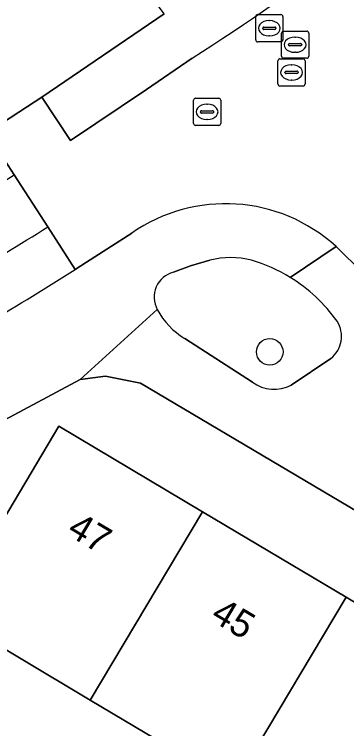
# Model space of a CAD drawing. Extents: x 161354 to 162026, y 386504 to 387460.
# Drawn here: x 161573.11 to 161585.34, y 386823.37 to 386849.65 of the extents above; entities that cross this region are included whole.
import ezdxf

# ---------------------------------------------------------------- set-up
doc = ezdxf.new("R2010")
doc.units = 0
for name, color, linetype in [('IMGEO_Boom', 7, 'Continuous'), ('IMGEO_Erf', 7, 'Continuous'), ('IMGEO_Groenvoorziening', 7, 'Continuous'), ('IMGEO_Pand', 7, 'Continuous'), ('IMGEO_Pand_nummerreeks', 7, 'Continuous'), ('IMGEO_Rijbaan_lokaal_gesloten', 7, 'Continuous'), ('IMGEO_Rijbaan_lokaal_open', 7, 'Continuous'), ('IMGEO_Rioolput', 7, 'Continuous'), ('IMGEO_Voetpad_open', 7, 'Continuous')]:
    doc.layers.add(name, color=color, linetype=linetype)

msp = doc.modelspace()

# ---------------------------------------------------------------- linework, layer by layer
at = {"layer": 'IMGEO_Boom'}
msp.add_circle((161582.505, 386837.229), 0.489, dxfattribs=at)
at = {"layer": 'IMGEO_Erf'}
for points in [[(161582.873, 386802.656), (161585.359, 386801.185), (161593.139, 386814.497), (161598.54, 386823.761), (161577.757, 386836.079), (161576.468, 386836.339), (161575.538, 386836.218), (161567.714, 386832.035), (161560.908, 386828.506), (161561.042, 386828.079), (161562.963, 386821.942), (161566.488, 386823.051), (161567.989, 386818.282), (161568.843, 386815.568), (161567.681, 386815.202), (161568.624, 386812.203), (161569.072, 386810.78), (161573.417, 386808.223), (161578.663, 386805.134)], [(161586.473, 386818.127), (161581.19, 386821.273), (161575.907, 386824.418), (161570.624, 386827.563), (161574.749, 386834.493), (161580.032, 386831.347), (161585.315, 386828.202), (161590.598, 386825.057), (161595.881, 386821.911), (161591.756, 386814.982)]]:
    msp.add_lwpolyline(points, close=True, dxfattribs=at)
at = {"layer": 'IMGEO_Groenvoorziening'}
for points in [[(161580.307, 386840.6), (161579.593, 386840.392), (161578.962, 386840.157)], [(161579.382, 386837.723), (161581.867, 386836.119)], [(161583.296, 386836.004), (161584.749, 386836.986)]]:
    msp.add_lwpolyline(points, dxfattribs=at)
for centre, radius, start, end in [((161581.073, 386837.677), 3.022, 75.3835, 104.6914), ((161580.176, 386834.963), 5.877, 58.3439, 73.5893), ((161579.203, 386839.24), 0.948, 104.7308, 208.3977), ((161580.163, 386834.932), 5.911, 35.4172, 58.4023), ((161580.785, 386840.071), 2.735, 207.9451, 239.1342), ((161584.12, 386837.797), 1.027, 307.8119, 33.0602), ((161582.672, 386837.183), 1.334, 232.8898, 297.9081)]:
    msp.add_arc(centre, radius, start, end, dxfattribs=at)
at = {"layer": 'IMGEO_Pand'}
for points in [[(161580.032, 386831.347), (161574.749, 386834.493), (161570.624, 386827.563), (161575.907, 386824.418)], [(161585.315, 386828.202), (161580.032, 386831.347), (161575.907, 386824.418), (161581.19, 386821.273)], [(161581.19, 386821.273), (161586.473, 386818.127), (161590.598, 386825.057), (161585.315, 386828.202)]]:
    msp.add_lwpolyline(points, close=True, dxfattribs=at)
at = {"layer": 'IMGEO_Rijbaan_lokaal_gesloten'}
for points in [[(161578.619, 386849.66), (161574.129, 386846.599), (161575.172, 386845.007), (161577.974, 386846.882), (161579.649, 386848.034)], [(161573.11, 386843.737), (161572.098, 386845.287), (161570.397, 386844.237)], [(161575.348, 386840.265), (161574.346, 386841.828)]]:
    msp.add_lwpolyline(points, dxfattribs=at)
for centre, radius, start, end in [((161538.721, 386912.606), 76.45, 302.3682, 313.17373), ((161483.765, 386989.11), 170.634, 294.48882, 301.57465), ((161507.605, 386948.155), 125.538, 298.78933, 302.11626), ((161526.3, 386916.738), 90.851, 298.00279, 302.67491)]:
    msp.add_arc(centre, radius, start, end, dxfattribs=at)
at = {"layer": 'IMGEO_Rijbaan_lokaal_open'}
for points in [[(161579.649, 386848.034), (161577.974, 386846.882), (161575.172, 386845.007), (161574.129, 386846.599), (161572.098, 386845.287), (161573.11, 386843.737), (161574.346, 386841.828), (161575.348, 386840.265), (161575.762, 386840.525), (161577.428, 386841.593)], [(161584.945, 386841.103), (161587.875, 386838.211), (161592.118, 386842.451), (161590.731, 386843.944)], [(161574.346, 386841.828), (161573.11, 386843.737)]]:
    msp.add_lwpolyline(points, dxfattribs=at)
for centre, radius, start, end in [((161538.721, 386912.606), 76.45, 302.3682, 313.17373), ((161483.765, 386989.11), 170.634, 294.48882, 301.57465), ((161580.88, 386836.646), 6.033, 47.6359, 124.905), ((161507.605, 386948.155), 125.538, 298.78933, 302.11626)]:
    msp.add_arc(centre, radius, start, end, dxfattribs=at)
at = {"layer": 'IMGEO_Rioolput'}
for p, q in [((161581.989, 386848.708), (161581.989, 386849.56)), ((161582.064, 386849.634), (161582.916, 386849.634)), ((161582.477, 386849.414), (161582.502, 386849.414)), ((161582.99, 386849.56), (161582.99, 386848.708)), ((161582.248, 386849.128), (161582.248, 386849.14)), ((161582.291, 386849.177), (161582.689, 386849.177)), ((161582.732, 386849.14), (161582.732, 386849.128)), ((161582.686, 386849.091), (161582.288, 386849.091)), ((161582.939, 386848.103), (161582.939, 386848.955)), ((161583.014, 386849.029), (161583.866, 386849.029)), ((161583.94, 386848.955), (161583.94, 386848.103)), ((161582.916, 386848.634), (161582.064, 386848.634)), ((161582.5, 386848.854), (161582.475, 386848.854)), ((161583.427, 386848.809), (161583.452, 386848.809)), ((161583.198, 386848.523), (161583.198, 386848.535)), ((161583.636, 386848.486), (161583.238, 386848.486)), ((161583.241, 386848.572), (161583.639, 386848.572)), ((161583.682, 386848.535), (161583.682, 386848.523)), ((161583.45, 386848.249), (161583.425, 386848.249)), ((161582.807, 386847.083), (161582.807, 386847.935)), ((161582.882, 386848.009), (161583.734, 386848.009)), ((161583.866, 386848.029), (161583.014, 386848.029)), ((161583.808, 386847.935), (161583.808, 386847.083)), ((161583.295, 386847.789), (161583.32, 386847.789)), ((161583.066, 386847.503), (161583.066, 386847.515)), ((161583.504, 386847.466), (161583.106, 386847.466)), ((161583.109, 386847.552), (161583.507, 386847.552)), ((161583.55, 386847.515), (161583.55, 386847.503)), ((161583.318, 386847.229), (161583.293, 386847.229)), ((161583.734, 386847.009), (161582.882, 386847.009)), ((161579.776, 386846.557), (161580.628, 386846.557)), ((161579.701, 386845.631), (161579.701, 386846.483)), ((161580.189, 386846.337), (161580.214, 386846.337)), ((161580.702, 386846.483), (161580.702, 386845.631)), ((161579.96, 386846.051), (161579.96, 386846.063)), ((161580.398, 386846.014), (161580, 386846.014)), ((161580.003, 386846.1), (161580.401, 386846.1)), ((161580.444, 386846.063), (161580.444, 386846.051)), ((161580.212, 386845.777), (161580.187, 386845.777)), ((161580.628, 386845.557), (161579.776, 386845.557))]:
    msp.add_line(p, q, dxfattribs=at)
for points in [[(161581.989, 386848.708), (161581.989, 386849.56)], [(161582.064, 386849.634), (161582.916, 386849.634)], [(161582.99, 386849.56), (161582.99, 386848.708)], [(161582.939, 386848.103), (161582.939, 386848.955)], [(161583.014, 386849.029), (161583.866, 386849.029)], [(161583.94, 386848.955), (161583.94, 386848.103)], [(161582.916, 386848.634), (161582.064, 386848.634)], [(161582.807, 386847.083), (161582.807, 386847.935)], [(161582.882, 386848.009), (161583.734, 386848.009)], [(161583.866, 386848.029), (161583.014, 386848.029)], [(161583.808, 386847.935), (161583.808, 386847.083)], [(161583.734, 386847.009), (161582.882, 386847.009)], [(161579.776, 386846.557), (161580.628, 386846.557)], [(161579.701, 386845.631), (161579.701, 386846.483)], [(161580.702, 386846.483), (161580.702, 386845.631)], [(161580.628, 386845.557), (161579.776, 386845.557)]]:
    msp.add_lwpolyline(points, dxfattribs=at)
for centre, radius, start, end in [((161582.066, 386849.558), 0.0765, 91.552, 178.448), ((161582.066, 386849.558), 0.0765, 91.552, 178.448), ((161582.914, 386849.558), 0.0765, 1.552, 88.448), ((161582.914, 386849.558), 0.0765, 1.552, 88.448), ((161582.288, 386849.137), 0.0403, 85.8775, 175.7526), ((161582.693, 386849.139), 0.0386, 1.7309, 96.639), ((161582.285, 386849.127), 0.0366, 178.938, 274.7102), ((161582.689, 386849.134), 0.043, 264.8664, 352.4533), ((161583.016, 386848.953), 0.0765, 91.552, 178.448), ((161583.016, 386848.953), 0.0765, 91.552, 178.448), ((161583.864, 386848.953), 0.0765, 1.552, 88.448), ((161583.864, 386848.953), 0.0765, 1.552, 88.448), ((161582.066, 386848.71), 0.0765, 181.552, 268.448), ((161582.066, 386848.71), 0.0765, 181.552, 268.448), ((161582.914, 386848.71), 0.0765, 271.552, 358.448), ((161582.914, 386848.71), 0.0765, 271.552, 358.448), ((161583.238, 386848.532), 0.0403, 85.8775, 175.7526), ((161583.235, 386848.522), 0.0366, 178.938, 274.7102), ((161583.639, 386848.529), 0.043, 264.8664, 352.4533), ((161583.643, 386848.534), 0.0386, 1.7309, 96.639), ((161583.016, 386848.105), 0.0765, 181.552, 268.448), ((161583.016, 386848.105), 0.0765, 181.552, 268.448), ((161583.864, 386848.105), 0.0765, 271.552, 358.448), ((161583.864, 386848.105), 0.0765, 271.552, 358.448), ((161582.884, 386847.933), 0.0765, 91.552, 178.448), ((161582.884, 386847.933), 0.0765, 91.552, 178.448), ((161583.732, 386847.933), 0.0765, 1.552, 88.448), ((161583.732, 386847.933), 0.0765, 1.552, 88.448), ((161583.106, 386847.512), 0.0403, 85.8775, 175.7526), ((161583.103, 386847.502), 0.0366, 178.938, 274.7102), ((161583.507, 386847.509), 0.043, 264.8664, 352.4533), ((161583.511, 386847.514), 0.0386, 1.7309, 96.639), ((161582.884, 386847.085), 0.0765, 181.552, 268.448), ((161582.884, 386847.085), 0.0765, 181.552, 268.448), ((161583.732, 386847.085), 0.0765, 271.552, 358.448), ((161583.732, 386847.085), 0.0765, 271.552, 358.448), ((161579.778, 386846.481), 0.0765, 91.552, 178.448), ((161579.778, 386846.481), 0.0765, 91.552, 178.448), ((161580.626, 386846.481), 0.0765, 1.552, 88.448), ((161580.626, 386846.481), 0.0765, 1.552, 88.448), ((161580, 386846.06), 0.0403, 85.8775, 175.7526), ((161579.997, 386846.05), 0.0366, 178.938, 274.7102), ((161580.401, 386846.057), 0.043, 264.8664, 352.4533), ((161580.405, 386846.062), 0.0386, 1.7309, 96.639), ((161579.778, 386845.633), 0.0765, 181.552, 268.448), ((161579.778, 386845.633), 0.0765, 181.552, 268.448), ((161580.626, 386845.633), 0.0765, 271.552, 358.448), ((161580.626, 386845.633), 0.0765, 271.552, 358.448)]:
    msp.add_arc(centre, radius, start, end, dxfattribs=at)
for centre, major_axis, ratio, start_param, end_param in [((161582.476, 386849.134), (-0.387, 0.002), 0.722429, 4.712389, 7.853982), ((161582.501, 386849.134), (-0.39, 0.002), 0.717154, 1.570796, 4.712389), ((161583.426, 386848.529), (-0.387, 0.002), 0.722429, 4.712389, 7.853982), ((161583.451, 386848.529), (-0.39, 0.002), 0.717154, 1.570796, 4.712389), ((161583.294, 386847.509), (-0.387, 0.002), 0.722429, 4.712389, 7.853982), ((161583.319, 386847.509), (-0.39, 0.002), 0.717154, 1.570796, 4.712389), ((161580.188, 386846.057), (-0.387, 0.002), 0.722429, 4.712389, 7.853982), ((161580.213, 386846.057), (-0.39, 0.002), 0.717154, 1.570796, 4.712389)]:
    msp.add_ellipse(centre, major_axis=major_axis, ratio=ratio, start_param=start_param, end_param=end_param, dxfattribs=at)
at = {"layer": 'IMGEO_Voetpad_open'}
for points in [[(161568.96, 386845.55), (161569.028, 386845.902), (161570.963, 386847.086), (161572.098, 386845.287), (161574.129, 386846.599), (161578.619, 386849.66), (161577.587, 386851.069), (161577.369, 386851.367)], [(161577.428, 386841.593), (161575.762, 386840.525), (161575.348, 386840.265)], [(161587.875, 386838.211), (161584.945, 386841.103), (161583.26, 386839.966)], [(161583.26, 386839.966), (161584.945, 386841.103)], [(161578.962, 386840.157), (161579.593, 386840.392), (161580.307, 386840.6)], [(161456.002, 386814.546), (161464.091, 386813.825), (161468.207, 386813.635), (161476.197, 386813.244), (161491.134, 386812.564), (161492.529, 386812.499), (161524.007, 386811.339), (161524, 386811.032), (161526.977, 386810.897), (161527.182, 386817.104), (161535.478, 386819.618), (161535.157, 386820.828), (161536.276, 386821.142), (161536.643, 386819.971), (161537.374, 386820.193), (161541.76, 386821.49), (161548.555, 386824.146), (161560.908, 386828.506), (161567.714, 386832.035), (161575.538, 386836.218), (161578.369, 386838.789)], [(161578.369, 386838.789), (161575.538, 386836.218), (161576.468, 386836.339), (161577.757, 386836.079), (161598.54, 386823.761)], [(161581.867, 386836.119), (161579.382, 386837.723)], [(161584.749, 386836.986), (161583.296, 386836.004)]]:
    msp.add_lwpolyline(points, dxfattribs=at)
for centre, radius, start, end in [((161580.88, 386836.646), 6.033, 47.6359, 124.905), ((161581.073, 386837.677), 3.022, 75.3835, 104.6914), ((161580.176, 386834.963), 5.877, 58.3439, 73.5893), ((161526.3, 386916.738), 90.851, 298.00279, 302.67491), ((161579.203, 386839.24), 0.948, 104.7308, 208.3977), ((161580.163, 386834.932), 5.911, 35.4172, 58.4023), ((161580.785, 386840.071), 2.735, 207.9451, 239.1342), ((161584.12, 386837.797), 1.027, 307.8119, 33.0602), ((161582.672, 386837.183), 1.334, 232.8898, 297.9081)]:
    msp.add_arc(centre, radius, start, end, dxfattribs=at)

# ---------------------------------------------------------------- texts
at = {"layer": 'IMGEO_Pand_nummerreeks'}
for s, p in [('47', (161575.003, 386830.524)), ('45', (161580.286, 386827.379))]:
    msp.add_text(s, height=1, rotation=329.2304, dxfattribs=at).set_placement(p)

doc.saveas('drawing.dxf')
